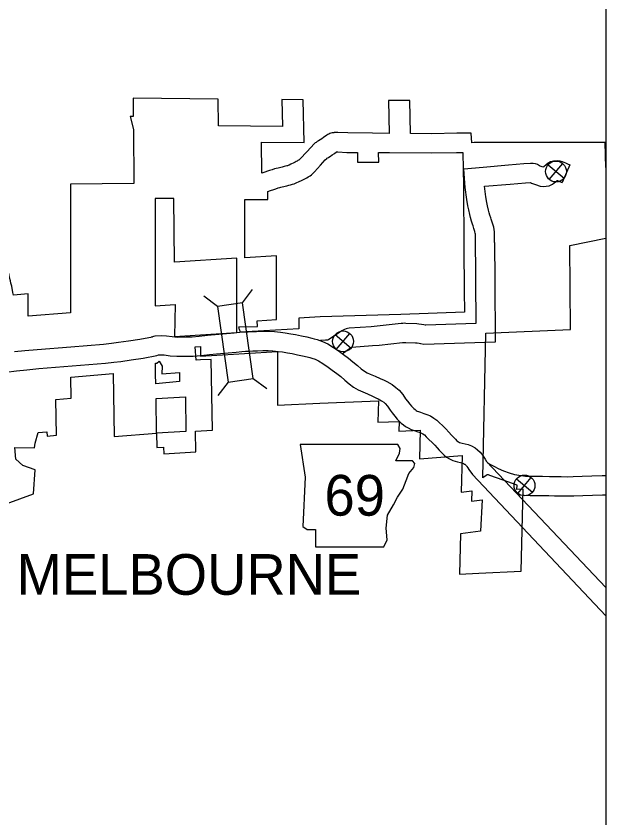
# Model space of a CAD drawing. Extents: x 1377389 to 1380723, y 1168351 to 1170484.
# Drawn here: x 1378187.3 to 1378279.2, y 1169773.2 to 1169898.1 of the extents above; entities that cross this region are included whole.
import ezdxf

# ---------------------------------------------------------------- set-up
doc = ezdxf.new("R2010")
doc.units = 0
doc.layers.add('B_Fill', color=7, linetype='Continuous')
doc.layers.add('B_Text', color=7, linetype='Continuous')

msp = doc.modelspace()

# ---------------------------------------------------------------- linework, layer by layer
at = {"layer": 'B_Fill'}
for p, q in [((1378270.13, 1169874.92), (1378272.62, 1169872.83)), ((1378270.33, 1169872.63), (1378272.42, 1169875.12)), ((1378273.55, 1169874.88), (1378272.32, 1169872.14)), ((1378222.55, 1169853.41), (1378224.13, 1169855.52)), ((1378218.63, 1169852.85), (1378216.52, 1169854.44)), ((1378236.96, 1169848.47), (1378239.45, 1169846.38)), ((1378237.16, 1169846.18), (1378239.25, 1169848.67)), ((1378224.22, 1169841.64), (1378226.33, 1169840.06)), ((1378220.3, 1169841.09), (1378218.71, 1169838.98)), ((1378265.23, 1169826.04), (1378267.72, 1169823.95)), ((1378265.43, 1169823.75), (1378267.52, 1169826.24)), ((1378268.24, 1169826.43), (1378268.23, 1169826.43)), ((1378268.24, 1169823.43), (1378268.25, 1169823.43))]:
    msp.add_line(p, q, dxfattribs=at)
for points in [[(1378218.81, 1169880.99), (1378218.75, 1169885.15), (1378205.5, 1169885.27), (1378205.53, 1169882.44), (1378205.07, 1169882.43), (1378205.55, 1169880.43), (1378205.64, 1169872), (1378195.74, 1169871.9)], [(1378225.57, 1169873.62), (1378225.49, 1169878.44), (1378232.13, 1169878.38), (1378232, 1169885.02), (1378228.69, 1169885.05), (1378228.76, 1169880.89), (1378218.81, 1169880.99)], [(1378258.25, 1169878.35), (1378258.16, 1169879.82), (1378255.92, 1169879.82), (1378252.03, 1169879.75), (1378248.71, 1169879.77), (1378248.61, 1169884.9), (1378245.29, 1169884.92), (1378245.39, 1169879.8), (1378242.8, 1169879.86), (1378238.93, 1169879.9), (1378237.42, 1169879.93), (1378237.21, 1169879.93), (1378237.03, 1169879.93), (1378236.94, 1169879.93), (1378236.85, 1169879.92), (1378236.78, 1169879.91), (1378236.66, 1169879.9), (1378236.49, 1169879.87), (1378236.29, 1169879.82), (1378236.15, 1169879.77), (1378235.99, 1169879.7), (1378235.83, 1169879.62), (1378235.66, 1169879.52), (1378235.17, 1169879.16), (1378234.89, 1169878.97), (1378234.62, 1169878.8), (1378234.39, 1169878.66), (1378234.17, 1169878.52), (1378234.01, 1169878.4), (1378233.87, 1169878.32), (1378233.65, 1169878.13), (1378233.22, 1169877.68), (1378232.49, 1169876.86), (1378231.57, 1169875.9), (1378231.44, 1169875.76), (1378231.33, 1169875.66), (1378231.32, 1169875.65), (1378231.19, 1169875.57), (1378231.05, 1169875.48), (1378230.9, 1169875.4), (1378230.77, 1169875.33), (1378230.56, 1169875.23), (1378230.05, 1169874.99), (1378229.79, 1169874.87), (1378229.66, 1169874.82), (1378229.54, 1169874.77), (1378229.43, 1169874.73), (1378229.24, 1169874.68), (1378229.05, 1169874.63), (1378228.75, 1169874.56), (1378228.08, 1169874.41), (1378227.77, 1169874.33), (1378227.53, 1169874.27), (1378227.16, 1169874.15), (1378226.75, 1169874.01), (1378226.45, 1169873.9), (1378226, 1169873.76), (1378225.57, 1169873.62)], [(1378279.16, 1169874.51), (1378279.01, 1169878.39), (1378271.84, 1169878.38), (1378258.64, 1169878.36), (1378258.25, 1169878.35)], [(1378226.5, 1169870.77), (1378226.89, 1169870.89), (1378227.42, 1169871.06), (1378227.76, 1169871.18), (1378228.1, 1169871.3), (1378228.38, 1169871.39), (1378228.53, 1169871.43), (1378228.75, 1169871.49), (1378229.44, 1169871.64), (1378229.77, 1169871.72), (1378230.01, 1169871.78), (1378230.31, 1169871.87), (1378230.58, 1169871.96), (1378230.8, 1169872.04), (1378230.99, 1169872.13), (1378231.28, 1169872.25), (1378231.85, 1169872.52), (1378232.14, 1169872.66), (1378232.34, 1169872.77), (1378232.55, 1169872.88), (1378232.79, 1169873.03), (1378233.07, 1169873.21), (1378233.27, 1169873.37), (1378233.53, 1169873.61), (1378233.74, 1169873.82), (1378234.7, 1169874.83), (1378235.44, 1169875.66), (1378235.68, 1169875.91), (1378235.69, 1169875.92), (1378235.83, 1169876.02), (1378235.98, 1169876.11), (1378236.23, 1169876.27), (1378236.52, 1169876.46), (1378236.89, 1169876.69), (1378237.21, 1169876.93), (1378237.39, 1169876.93), (1378238.8, 1169876.84), (1378240.45, 1169876.83), (1378240.48, 1169875.33), (1378243.78, 1169875.31), (1378243.75, 1169876.81), (1378245.44, 1169876.8), (1378252.04, 1169876.75), (1378255.9, 1169876.82), (1378256.84, 1169876.82), (1378256.95, 1169871.61)], [(1378257.04, 1169874.3), (1378260.02, 1169874.56), (1378264, 1169874.89), (1378266.38, 1169875.09), (1378267.4, 1169875.18), (1378267.81, 1169875.18), (1378268.13, 1169875.1), (1378268.48, 1169875), (1378268.79, 1169874.82), (1378268.88, 1169874.77), (1378269.16, 1169874.65), (1378269.4, 1169874.58), (1378269.49, 1169874.66), (1378269.84, 1169874.98), (1378270.16, 1169875.22), (1378270.53, 1169875.41), (1378270.98, 1169875.55), (1378271.53, 1169875.59), (1378271.96, 1169875.53), (1378272.34, 1169875.43), (1378272.84, 1169875.2), (1378273.18, 1169875.05), (1378273.55, 1169874.88)], [(1378257.23, 1169871.35), (1378257.04, 1169874.3)], [(1378195.74, 1169871.9), (1378195.75, 1169851.89), (1378189.15, 1169851.36), (1378189.15, 1169854.8), (1378186.89, 1169854.63), (1378186.79, 1169855.02), (1378186.61, 1169856.02), (1378186.48, 1169856.5), (1378186.39, 1169856.87), (1378186.25, 1169857.35), (1378186.13, 1169858.03), (1378182.52, 1169857.79), (1378181.59, 1169857.79)], [(1378256.95, 1169871.61), (1378257.03, 1169861.96), (1378257.09, 1169855.28), (1378257.12, 1169851.95), (1378247.21, 1169851.63), (1378234.62, 1169851.22), (1378231.32, 1169851.02), (1378231.31, 1169849.39), (1378222.23, 1169848.83)], [(1378260.23, 1169871.56), (1378264.25, 1169871.9), (1378266.63, 1169872.1), (1378267.39, 1169872.16), (1378267.58, 1169872.06), (1378268.17, 1169871.82), (1378268.91, 1169871.6), (1378269.38, 1169871.53), (1378269.84, 1169871.56), (1378270.31, 1169871.65), (1378270.83, 1169871.9), (1378271.1, 1169872.11), (1378271.43, 1169872.36), (1378271.56, 1169872.49), (1378271.6, 1169872.47), (1378271.94, 1169872.31), (1378272.32, 1169872.14)], [(1378261.8, 1169862.8), (1378261.78, 1169864.48), (1378261.67, 1169865.19), (1378261.49, 1169865.82), (1378261.4, 1169866.14), (1378261.29, 1169866.44), (1378261.21, 1169866.65), (1378261.08, 1169867.05), (1378260.96, 1169867.44), (1378260.88, 1169867.83), (1378260.72, 1169868.51), (1378260.62, 1169869.04), (1378260.47, 1169869.94), (1378260.23, 1169871.56)], [(1378222.23, 1169848.83), (1378222.08, 1169849.27), (1378222.04, 1169849.39), (1378222.01, 1169849.52), (1378221.99, 1169849.61), (1378221.99, 1169849.67), (1378224.88, 1169849.72), (1378224.85, 1169850.63), (1378227.84, 1169850.81), (1378227.85, 1169860.75), (1378222.91, 1169860.44), (1378222.89, 1169869.52), (1378226.51, 1169869.49), (1378226.5, 1169870.77)], [(1378258.78, 1169864.2), (1378258.78, 1169864.24), (1378258.74, 1169864.54), (1378258.6, 1169865.01), (1378258.55, 1169865.21), (1378258.48, 1169865.39), (1378258.37, 1169865.68), (1378258.22, 1169866.16), (1378258.06, 1169866.68), (1378257.95, 1169867.17), (1378257.79, 1169867.88), (1378257.66, 1169868.52), (1378257.51, 1169869.49), (1378257.23, 1169871.35)], [(1378221.69, 1169848.79), (1378221.66, 1169860.35), (1378211.94, 1169859.73), (1378211.86, 1169869.67), (1378208.94, 1169869.68)], [(1378208.94, 1169869.68), (1378208.94, 1169859.54), (1378208.94, 1169852.95), (1378212.06, 1169853.14), (1378211.95, 1169848.19), (1378221.69, 1169848.79)], [(1378258.78, 1169864.2), (1378258.83, 1169856.92)], [(1378260.45, 1169848.72), (1378273.63, 1169849.25), (1378273.64, 1169849.25), (1378273.53, 1169862.37), (1378279.16, 1169863.48)], [(1378261.8, 1169862.8), (1378261.83, 1169856.95)], [(1378258.83, 1169856.92), (1378258.89, 1169850.21), (1378251.12, 1169849.95), (1378251, 1169849.97), (1378250.81, 1169850.01), (1378250.43, 1169850.07), (1378250, 1169850.11), (1378249.69, 1169850.14), (1378247.97, 1169850.21), (1378247.74, 1169850.23), (1378247.51, 1169850.19), (1378247.26, 1169850.19), (1378243.52, 1169849.79), (1378242.59, 1169849.71), (1378239.17, 1169849.47), (1378238.91, 1169849.43), (1378238.7, 1169849.36), (1378238.42, 1169849.26), (1378238, 1169849.05), (1378237.72, 1169848.86), (1378235.94, 1169847.64), (1378235.78, 1169847.62), (1378235.56, 1169847.6), (1378235.45, 1169847.59), (1378234.68, 1169847.55)], [(1378261.83, 1169856.95), (1378261.92, 1169847.32), (1378250.8, 1169846.93), (1378250.33, 1169847.05), (1378250.28, 1169847.06), (1378250.07, 1169847.09), (1378249.75, 1169847.12), (1378249.5, 1169847.14), (1378248.01, 1169847.2), (1378247.45, 1169847.19), (1378243.81, 1169846.8), (1378242.82, 1169846.72), (1378239.59, 1169846.49), (1378239.53, 1169846.47), (1378239.42, 1169846.39), (1378238.05, 1169845.44)], [(1378208.35, 1169848.11), (1378208.92, 1169848.3), (1378209.97, 1169848.35), (1378210.71, 1169848.29), (1378211.59, 1169848.16), (1378212.42, 1169848.1), (1378213.73, 1169848.11), (1378214.72, 1169848.12), (1378215.79, 1169848.21), (1378217.12, 1169848.39), (1378218.27, 1169848.47), (1378221.23, 1169848.73), (1378222.11, 1169848.86), (1378222.88, 1169848.91), (1378223.41, 1169848.92), (1378224.07, 1169848.94), (1378224.73, 1169848.97), (1378225.64, 1169849.01), (1378226.67, 1169848.99), (1378227.55, 1169848.95), (1378228.47, 1169848.83), (1378229.21, 1169848.73), (1378230.05, 1169848.59), (1378230.81, 1169848.47), (1378231.72, 1169848.28), (1378232.55, 1169848.11), (1378233.33, 1169847.91), (1378233.71, 1169847.83), (1378234.2, 1169847.71), (1378235.01, 1169847.42), (1378235.85, 1169847.03), (1378236.73, 1169846.48), (1378237.64, 1169845.84), (1378238.29, 1169845.38), (1378239.06, 1169844.8), (1378239.74, 1169844.25), (1378240.46, 1169843.66), (1378241.05, 1169843.14), (1378241.54, 1169842.77), (1378241.94, 1169842.54), (1378242.45, 1169842.32), (1378243.23, 1169841.98), (1378244, 1169841.65), (1378244.6, 1169841.37), (1378245.03, 1169841.16), (1378245.85, 1169840.71), (1378246.45, 1169840.26), (1378246.94, 1169839.83), (1378247.51, 1169839.13), (1378247.95, 1169838.48), (1378248.25, 1169838.11), (1378248.59, 1169837.66), (1378248.86, 1169837.34), (1378249.24, 1169836.96), (1378249.46, 1169836.79), (1378249.62, 1169836.67), (1378249.76, 1169836.58), (1378249.96, 1169836.49), (1378250.26, 1169836.38), (1378250.77, 1169836.21), (1378251.24, 1169836.06), (1378251.81, 1169835.84), (1378252.36, 1169835.49), (1378252.83, 1169835.13), (1378253.23, 1169834.74), (1378253.69, 1169834.31), (1378254.22, 1169833.78), (1378254.69, 1169833.3), (1378255.1, 1169832.83), (1378255.4, 1169832.49), (1378255.7, 1169832.18), (1378255.94, 1169831.95), (1378256.06, 1169831.85), (1378256.19, 1169831.77), (1378256.36, 1169831.7), (1378256.78, 1169831.58), (1378257.23, 1169831.47), (1378257.69, 1169831.35), (1378258.2, 1169831.16), (1378258.76, 1169830.86), (1378259.16, 1169830.55), (1378259.57, 1169830.16), (1378259.78, 1169829.93), (1378259.97, 1169829.66), (1378260.15, 1169829.39), (1378260.34, 1169829.08), (1378260.55, 1169828.74)], [(1378187.03, 1169845.84), (1378188.67, 1169845.98), (1378190.59, 1169846.17), (1378195.8, 1169846.58), (1378200.92, 1169847), (1378202.14, 1169847.14), (1378203.21, 1169847.28), (1378204.78, 1169847.5), (1378206.56, 1169847.74), (1378208.52, 1169848.15)], [(1378259.97, 1169826.19), (1378260.45, 1169848.72)], [(1378215.21, 1169833.45), (1378217.87, 1169833.59), (1378217.69, 1169844.6), (1378215.99, 1169844.54), (1378215.33, 1169844.5), (1378215.19, 1169846.58), (1378215.99, 1169846.63), (1378215.99, 1169845.13)], [(1378185.72, 1169842.64), (1378187.35, 1169842.85), (1378188.94, 1169842.99), (1378190.85, 1169843.18), (1378196.04, 1169843.59), (1378201.21, 1169844.02), (1378202.5, 1169844.16), (1378203.62, 1169844.3), (1378205.2, 1169844.53), (1378207.07, 1169844.79), (1378209.21, 1169845.23)], [(1378209.21, 1169845.23), (1378209.48, 1169845.32), (1378209.93, 1169845.34), (1378210.37, 1169845.31), (1378211.27, 1169845.18), (1378212.32, 1169845.1), (1378213.75, 1169845.11), (1378214.85, 1169845.12), (1378216.11, 1169845.22), (1378217.43, 1169845.4), (1378218.52, 1169845.48), (1378221.58, 1169845.75), (1378222.42, 1169845.87), (1378223, 1169845.91), (1378223.49, 1169845.92), (1378224.18, 1169845.94), (1378224.86, 1169845.97), (1378225.69, 1169846.01), (1378226.56, 1169845.99), (1378227.28, 1169845.96), (1378228.09, 1169845.86), (1378228.76, 1169845.77), (1378229.57, 1169845.63), (1378230.28, 1169845.52), (1378231.1, 1169845.35), (1378231.88, 1169845.18), (1378232.64, 1169844.99), (1378233.04, 1169844.9), (1378233.34, 1169844.83), (1378233.87, 1169844.64), (1378234.41, 1169844.39), (1378235.07, 1169843.98), (1378235.9, 1169843.39), (1378236.52, 1169842.95), (1378237.23, 1169842.42), (1378237.85, 1169841.93), (1378238.51, 1169841.37), (1378239.16, 1169840.81), (1378239.86, 1169840.28), (1378240.57, 1169839.86), (1378241.27, 1169839.56), (1378242.04, 1169839.23), (1378242.77, 1169838.91), (1378243.32, 1169838.65), (1378243.67, 1169838.49), (1378244.22, 1169838.18), (1378244.55, 1169837.94), (1378244.76, 1169837.75), (1378245.11, 1169837.33), (1378245.53, 1169836.71), (1378245.87, 1169836.28), (1378246.25, 1169835.78), (1378246.66, 1169835.29), (1378247.26, 1169834.7), (1378247.63, 1169834.41), (1378247.92, 1169834.19), (1378248.33, 1169833.94), (1378248.81, 1169833.71), (1378249.28, 1169833.55), (1378249.84, 1169833.36), (1378250.24, 1169833.24), (1378250.44, 1169833.15), (1378250.65, 1169833.02), (1378250.87, 1169832.85), (1378251.16, 1169832.58), (1378251.59, 1169832.16), (1378252.08, 1169831.67), (1378252.5, 1169831.24), (1378252.86, 1169830.85), (1378253.19, 1169830.47), (1378253.57, 1169830.06), (1378253.95, 1169829.7), (1378254.33, 1169829.39), (1378254.8, 1169829.11), (1378255.33, 1169828.87), (1378256.03, 1169828.67), (1378256.5, 1169828.56), (1378256.76, 1169828.49), (1378256.97, 1169828.41), (1378257.13, 1169828.33), (1378257.2, 1169828.28), (1378257.41, 1169828.07), (1378257.43, 1169828.05), (1378257.51, 1169827.93), (1378257.65, 1169827.74), (1378257.82, 1169827.46), (1378258.37, 1169826.68)], [(1378215.99, 1169845.13), (1378228, 1169845.87)], [(1378228, 1169845.87), (1378227.99, 1169837.47)], [(1378208.98, 1169844.03), (1378209.22, 1169844.05), (1378209.55, 1169844.35), (1378210.01, 1169843.58), (1378209.99, 1169842.39), (1378212.72, 1169842.6), (1378212.74, 1169841.18)], [(1378212.74, 1169841.18), (1378209.04, 1169840.81), (1378209.01, 1169842.32), (1378208.98, 1169844.03)], [(1378183.69, 1169820.93), (1378185.72, 1169822.12), (1378189.98, 1169823.67), (1378190.25, 1169827.41), (1378188.33, 1169828.08), (1378187.23, 1169829.09), (1378187.07, 1169830.88), (1378190.14, 1169830.83), (1378190.26, 1169831.56), (1378190.7, 1169833.23), (1378192.09, 1169833.34), (1378192.1, 1169832.68), (1378193.58, 1169832.81), (1378193.49, 1169838.36), (1378195.87, 1169838.57), (1378195.82, 1169841.84), (1378202.41, 1169842.44), (1378202.58, 1169832.59), (1378209.17, 1169833.14)], [(1378209.08, 1169838.53), (1378213.66, 1169838.8), (1378213.74, 1169833.38)], [(1378209.17, 1169833.14), (1378209.08, 1169838.53)], [(1378227.99, 1169837.47), (1378234.6, 1169837.82), (1378243.72, 1169838.15), (1378243.65, 1169834.82), (1378246.95, 1169834.96), (1378246.92, 1169833.43), (1378250.22, 1169833.6), (1378250.13, 1169829.13), (1378256.74, 1169829.68), (1378256.62, 1169823.95)], [(1378213.74, 1169833.38), (1378209.17, 1169833.14)], [(1378209.17, 1169833.14), (1378209.21, 1169830.89)], [(1378209.21, 1169830.89), (1378210.26, 1169830.95), (1378210.28, 1169829.9), (1378215.27, 1169830.2), (1378215.21, 1169833.45)], [(1378260.55, 1169828.74), (1378279.16, 1169809.09)], [(1378260.77, 1169828.51), (1378260.95, 1169828.36), (1378261.15, 1169828.26), (1378261.77, 1169827.93), (1378262.38, 1169827.64), (1378263.18, 1169827.29), (1378264.07, 1169826.97), (1378264.93, 1169826.71), (1378265.25, 1169826.65), (1378265.57, 1169826.58), (1378265.96, 1169826.52), (1378266.63, 1169826.46), (1378267.42, 1169826.43), (1378268.24, 1169826.43)], [(1378258.37, 1169826.68), (1378279.16, 1169804.72)], [(1378266.28, 1169824.4), (1378265.29, 1169824.35), (1378265.31, 1169825.06), (1378263.14, 1169825.82), (1378261.08, 1169826.55), (1378260.94, 1169826.6), (1378260.86, 1169826.62), (1378260.79, 1169826.63), (1378260.7, 1169826.64), (1378260.65, 1169826.64), (1378260.62, 1169826.63), (1378260.58, 1169826.62), (1378260.55, 1169826.6), (1378260.49, 1169826.56), (1378259.97, 1169826.19)], [(1378268.23, 1169826.43), (1378269.26, 1169826.43), (1378270.36, 1169826.41), (1378271.2, 1169826.37), (1378272.2, 1169826.37), (1378273.13, 1169826.35), (1378274.03, 1169826.36), (1378275.43, 1169826.45), (1378276.98, 1169826.48), (1378278.55, 1169826.52), (1378279.16, 1169826.53)], [(1378256.34, 1169811.16), (1378259.33, 1169811.34), (1378265.97, 1169811.63), (1378266.28, 1169824.4)], [(1378256.62, 1169823.95), (1378258.27, 1169824.16), (1378258.22, 1169822.53), (1378259.85, 1169822.73), (1378259.63, 1169817.85), (1378256.48, 1169817.45), (1378256.34, 1169811.16)], [(1378265.46, 1169823.55), (1378266.43, 1169823.47), (1378267.36, 1169823.43), (1378268.24, 1169823.43)], [(1378268.25, 1169823.43), (1378269.24, 1169823.43), (1378270.26, 1169823.41), (1378271.13, 1169823.37), (1378272.17, 1169823.37), (1378273.12, 1169823.35), (1378274.14, 1169823.36), (1378275.57, 1169823.45), (1378277.05, 1169823.49), (1378278.6, 1169823.52), (1378279.16, 1169823.53)]]:
    msp.add_lwpolyline(points, dxfattribs=at)
for points in [[(1378224.22, 1169841.64), (1378222.55, 1169853.41), (1378218.63, 1169852.85), (1378220.3, 1169841.09)], [(1378231.53, 1169831.35), (1378232.29, 1169826.28), (1378231.96, 1169818.58), (1378232.63, 1169818.16), (1378233.9, 1169818.16), (1378233.9, 1169815.45), (1378244.56, 1169815.45), (1378245.07, 1169816.55), (1378244.9, 1169818.33), (1378245.15, 1169820.36), (1378246.08, 1169821.96), (1378246.67, 1169823.15), (1378247.52, 1169824.42), (1378248.03, 1169825.77), (1378248.45, 1169826.87), (1378249.21, 1169827.8), (1378249.38, 1169828.39), (1378249.04, 1169828.82), (1378246.42, 1169828.82), (1378247.01, 1169830), (1378247.1, 1169830.76), (1378246.75, 1169831.35)]]:
    msp.add_lwpolyline(points, close=True, dxfattribs=at)
for centre in [(1378271.37, 1169873.87), (1378238.21, 1169847.42), (1378266.47, 1169824.99)]:
    msp.add_circle(centre, 1.62, dxfattribs=at)
at = {"layer": 'B_Text'}
msp.add_lwpolyline([(1377549.76, 1170388.77), (1378279.16, 1170388.77), (1378279.16, 1169604.28), (1377549.76, 1169604.28)], close=True, dxfattribs=at)

# ---------------------------------------------------------------- texts
at = {"layer": 'B_Fill'}
for s, p in [('69', (1378235.31, 1169820.29)), ('MELBOURNE', (1378187.37, 1169807.97))]:
    msp.add_text(s, height=6.336, dxfattribs=at).set_placement(p)

doc.saveas('drawing.dxf')
